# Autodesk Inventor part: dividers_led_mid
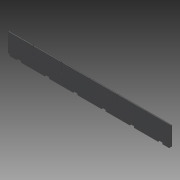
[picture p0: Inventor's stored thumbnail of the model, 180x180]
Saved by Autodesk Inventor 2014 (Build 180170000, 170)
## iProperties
Created: 2014-05
Part Number: dividers_led_mid
Material: ABS Plastic
Document SubType Name: Modeling
Designer: t_emanb
Density: 1 g/cm^3
Appearance: Smooth - White
Author: t_emanb
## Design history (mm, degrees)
sketch "Sketch1"
  geometry: L1 (0, 0)-(584.2, 0); L2 (584.2, 0)-(584.2, 73.101); L3 (584.2, 73.101)-(0, 73.101); L4 (0, 73.101)-(0, 0)
  constraints: 8 end point, 2 parallel, 1 horizontal, 1 perpendicular
  dimensions: "d0" = 584.2 distance of L2.end L3.end; "d1" = 73.1012 distance of L3.end L1.start
extrude "Extrusion1" new body sketch "Sketch1" distance "d2" = 3.048; taper "d3" = 0 deg
sketch "Sketch2" dims "d9" = 25.4, "d20" = 25.4, "d32" = 25.4
  geometry: L1 (88.9, 73.101)-(88.9, 0); L2 (190.5, 73.101)-(190.5, 0); L3 (292.1, 73.101)-(292.1, 0); L4 (393.7, 73.101)-(393.7, 0); L5 (495.3, 73.101)-(495.3, 0); L6 (139.7, 73.101)-(139.7, 0); L7 (38.1, 0)-(38.1, 73.101); L8 (241.3, 0)-(241.3, 73.101); L9 (342.9, 73.101)-(342.9, 0); L10 (444.5, 0)-(444.5, 73.101); L11 (546.1, 73.101)-(546.1, 0); L12 (131.762, 0)-(147.638, 0); L13 (147.638, 0)-(147.638, 5.08); L14 (147.638, 5.08)-(131.763, 5.08); L15 (131.763, 5.08)-(131.762, 0); L16 (249.238, 5.08)-(233.363, 5.08); L17 (233.363, 5.08)-(233.363, 0); L18 (233.363, 0)-(249.238, 0); L19 (249.238, 0)-(249.238, 5.08); L20 (350.838, 5.08)-(334.963, 5.08); L21 (334.963, 5.08)-(334.963, 0); L22 (334.963, 0)-(350.838, 0); L23 (350.838, 0)-(350.838, 5.08); L24 (452.438, 5.08)-(436.562, 5.08); L25 (436.562, 5.08)-(436.562, 0); L26 (436.562, 0)-(452.438, 0); L27 (452.438, 0)-(452.438, 5.08); L28 (554.038, 5.08)-(538.162, 5.08); L29 (538.162, 5.08)-(538.162, 0); L30 (538.162, 0)-(554.038, 0); L31 (554.038, 0)-(554.038, 5.08); L32 (30.163, 0)-(46.037, 0); L33 (46.037, 0)-(46.037, 5.08); L34 (46.037, 5.08)-(30.163, 5.08); L35 (30.163, 5.08)-(30.163, 0); L36 (87.376, 73.101)-(90.424, 73.101); L37 (90.424, 73.101)-(90.424, 38.1); L38 (90.424, 38.1)-(87.376, 38.1); L39 (87.376, 38.1)-(87.376, 73.101); L40 (188.976, 38.1)-(188.976, 73.101); L41 (188.976, 73.101)-(192.024, 73.101); L42 (192.024, 73.101)-(192.024, 38.1); L43 (192.024, 38.1)-(188.976, 38.1); L44 (290.576, 38.1)-(290.576, 73.101); L45 (290.576, 73.101)-(293.624, 73.101); L46 (293.624, 73.101)-(293.624, 38.1); L47 (293.624, 38.1)-(290.576, 38.1); L48 (392.176, 38.1)-(392.176, 73.101); L49 (392.176, 73.101)-(395.224, 73.101); L50 (395.224, 73.101)-(395.224, 38.1); L51 (395.224, 38.1)-(392.176, 38.1); L52 (493.776, 38.1)-(493.776, 73.101); L53 (493.776, 73.101)-(496.824, 73.101); L54 (496.824, 73.101)-(496.824, 38.1); L55 (496.824, 38.1)-(493.776, 38.1); 4 further points
  constraints: 110 end point, 40 horizontal alignment, 26 parallel, 16 collinear, 7 vertical, 3 horizontal, 3 perpendicular, 26 other
  dimensions: "d6" = 101.6 distance of L1.start L2.start; "d11" = 50.8 distance between parallel lines of L11 L5; "d12" = 50.8 distance between parallel lines of L1 L7; "d13" = 15.875 distance of L13.end L14.end; "d14" = 5.08 distance of L12.end L13.end; "d17" = 101.6 distance of L13.end L16.start; "d22" = 5.08 distance of L32.end L33.end; "d24" = 3.048 distance of L37.end L38.end; "d25" = 38.1 distance of the line from the sketch origin of L38; "d26" = 1.524 distance between parallel lines of L37 L1 (= 0.5 x d24); "d29" = 101.6 distance of L38.end L40.start; "d42" = 15.875 distance between parallel lines of L35 L33 (= d13)
extrude "Extrusion2" cut sketch "Sketch2" stored distance "d34" = 3.175; taper "d35" = 0 deg
sketch "Sketch3"
  geometry: L1 (554.038, 0)-(584.2, 0) reference; L2 (584.2, 0)-(584.2, 73.101) reference; L3 (0, 73.101)-(0, 0) reference; L4 (0, 0)-(30.163, 0) reference; L5 (538.162, 5.08)-(554.038, 5.08) reference; L6 (0, 6.35)-(6.35, 6.35); L7 (584.2, 6.35)-(577.85, 6.35); L8 (577.85, 6.35)-(577.85, 0); L9 (6.35, 6.35)-(6.35, 0)
  constraints: 8 end point, 4 point on line, 3 perpendicular, 1 parallel
  dimensions: "d36" = 6.35 distance of L7.start L7.end; "d37" = 6.35 distance of L6.start L6.end (= d36); "d38" = 6.35 distance of L7.end L8.end; "d39" = 6.35 distance of L6.end L9.end (= d38)
extrude "Extrusion3" cut sketch "Sketch3" stored distance "d40" = 25.4; taper "d41" = 0 deg
body "Solid1"
